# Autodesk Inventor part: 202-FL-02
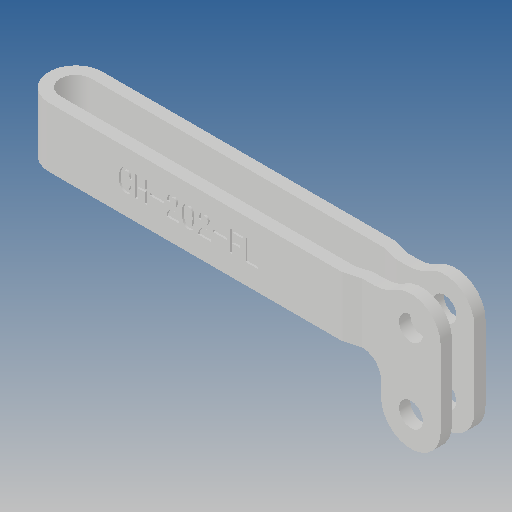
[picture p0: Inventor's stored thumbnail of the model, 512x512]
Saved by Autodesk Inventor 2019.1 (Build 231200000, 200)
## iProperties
Created: 2011-05
Part Number: 202-FL-02
Material: Ogólny
Document SubType Name: Modeling
Designer: CADENGINEERING4
Density: 1 g/cm^3
Appearance: Domyślna
Author: CADENGINEERING4
Revision Number: ÈÎºÎ
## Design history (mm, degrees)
feature "ÇÐ³ý-À­Éì5"
node "Bryła1"
